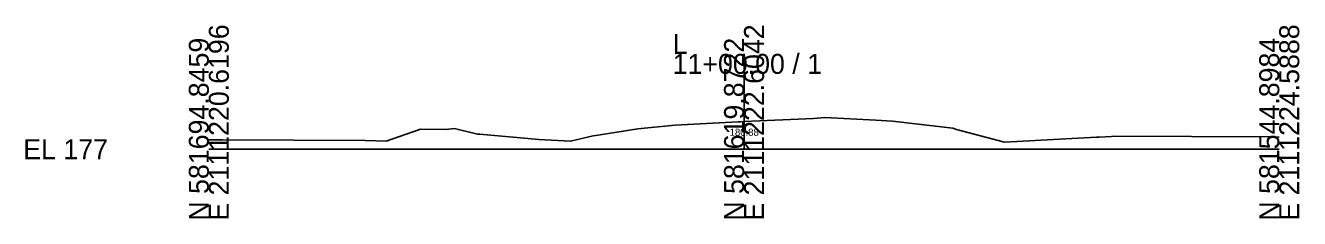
# Model space of a CAD drawing. Extents: x -26 to 3453, y -333 to 9539.
# Drawn here: x -25.7 to 152.8, y -9.7 to 17.3 of the extents above; entities that cross this region are included whole.
import ezdxf

# ---------------------------------------------------------------- set-up
doc = ezdxf.new("R2010")
doc.units = 0
for name, color, linetype in [('Default', 7, 'Continuous'), ('Exist Cross Section Cell', 7, 'Continuous'), ('Exist XS Center Line Elevation Label', 7, 'Continuous'), ('Exist XS Ground Line', 7, 'Continuous')]:
    doc.layers.add(name, color=color, linetype=linetype)

msp = doc.modelspace()

# ---------------------------------------------------------------- linework, layer by layer
at = {"layer": 'Exist Cross Section Cell'}
for p, q in [((75, 0), (75, 13.35)), ((0, 0), (75, 0)), ((75, 0), (150, 0))]:
    msp.add_line(p, q, dxfattribs=at)
at = {"layer": 'Exist XS Ground Line'}
for p, q in [((65.31, 3.36), (74.2, 3.84)), ((74.2, 3.84), (74.52, 3.86)), ((74.52, 3.86), (75, 3.88)), ((75, 3.88), (84.73, 4.29)), ((84.73, 4.29), (86.34, 4.45)), ((86.34, 4.45), (93.48, 4.09)), ((93.48, 4.09), (95.8, 3.92)), ((95.8, 3.92), (104.24, 2.93)), ((24.85, 1.15), (29.65, 2.8)), ((29.65, 2.8), (33.28, 2.78)), ((33.28, 2.78), (34.43, 2.89)), ((34.43, 2.89), (37.64, 2.1)), ((37.64, 2.1), (37.96, 2.12)), ((37.96, 2.12), (46.24, 1.36)), ((50.67, 1.13), (53.85, 1.86)), ((53.85, 1.86), (54.22, 1.91)), ((54.22, 1.91), (60.14, 2.84)), ((60.14, 2.84), (65.31, 3.36)), ((104.24, 2.93), (104.78, 2.75)), ((104.78, 2.75), (111.51, 0.97)), ((124.77, 1.68), (126.47, 1.8)), ((126.47, 1.8), (126.82, 1.83)), ((126.82, 1.83), (148.6, 1.72)), ((0, 1.34), (0.82, 1.32)), ((0.82, 1.32), (1.9, 1.31)), ((1.9, 1.31), (21.9, 1.21)), ((21.9, 1.21), (24.85, 1.15)), ((46.24, 1.36), (50.67, 1.13)), ((111.51, 0.97), (124.37, 1.67)), ((124.37, 1.67), (124.77, 1.68)), ((148.6, 1.72), (148.9, 1.72)), ((148.9, 1.72), (149.24, 1.72)), ((149.24, 1.72), (150, 1.68))]:
    msp.add_line(p, q, dxfattribs=at)

# ---------------------------------------------------------------- texts
at = {"layer": 'Default'}
msp.add_text('-', height=0.0001, dxfattribs=at).set_placement((0, 0))
at = {"layer": 'Exist Cross Section Cell'}
for s, p in [('E 2111220.6196', (2.8, -10)), ('E 2111222.6042', (77.8, -10)), ('E 2111224.5888', (152.8, -10)), ('N 581694.8459', (0, -10)), ('N 581619.8722', (75, -10)), ('N 581544.8984', (150, -10))]:
    msp.add_text(s, height=2.8, rotation=90, dxfattribs=at).set_placement(p)
for s, p in [('L', (65, 13.35)), ('11+00.00 / 1', (65, 10.55)), ('EL 177', (-26, -1.4))]:
    msp.add_text(s, height=2.8, dxfattribs=at).set_placement(p)
at = {"layer": 'Exist XS Center Line Elevation Label'}
msp.add_text('180.88', height=1, dxfattribs=at).set_placement((72.98, 1.88))

doc.saveas('drawing.dxf')
